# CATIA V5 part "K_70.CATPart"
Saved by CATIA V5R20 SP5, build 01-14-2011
Part number: 70
Bounding box of the stored display mesh (mm): x -28.492 to 28.492, y -60 to 120, z -28.492 to 28.492
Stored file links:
  G:\Khaled_CFAO_2011\ST2M\ST2M_GR1\lpierredon\Khaled\CAD_thinkMOTION\K_70.CATPart
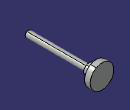
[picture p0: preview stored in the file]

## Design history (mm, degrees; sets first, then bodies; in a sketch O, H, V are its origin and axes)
Body1 (main body)
  Sketch1 on yz-plane, origin (0, 0, 0), H (0, 1, 0), V (0, 0, 1)
    line L1 (-60, 0) -> (-60, 7.5)
    point P1 (-60, 0)
    line L2 (88, 7.5) -> (-60, 7.5)
    line L3 (88, 7.5) -> (88, 12.5)
    line L4 (88, 12.5) -> (106, 12.5)
    line L5 (106, 12.5) -> (106, 28.5)
    line L6 (106, 28.5) -> (120, 28.5)
    line L7 (120, 28.5) -> (120, 0)
    point P8 (120, 0)
    line L8 (120, 0) -> (-60, 0)
    length L6 = 14
    length L4 = 18
    length L1 = 7.5
    length L3 = 5
    length L5 = 16
    length L8 = 180
    coincidence: P1 H, P8 H
    vertical: L1 V, L3 V, L5 V, L7 V
    horizontal: L2 H, L4 H, L6 H, L8 H
  Shaft1: profile Sketch1, axis Sketch1.L8, angle 360
  Chamfer1: length 1, angle 45, on edge [face of Shaft1 from Sketch1.L1 | face of Shaft1 from Sketch1.L2]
